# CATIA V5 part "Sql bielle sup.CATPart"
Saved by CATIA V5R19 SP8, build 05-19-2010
Part number: Sql bielle sup
Publications: "Droite.1", "Plan.1", "Droite.2", "Droite.3"
Bounding box of the stored display mesh (mm): x 100 to 400, y -20 to 20, z 0 to 0
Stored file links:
  C:\Users\ThinkMotion\Desktop\EU_thinkMotion\iao\IAO_MMS_Groupe3\rdalborgo\rdalborgo\Sql bielle sup.CATPart
  C:\Users\ThinkMotion\Desktop\EU_thinkMotion\iao\IAO_MMS_Groupe3\rdalborgo\rdalborgo\Sql train.CATProduct
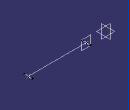
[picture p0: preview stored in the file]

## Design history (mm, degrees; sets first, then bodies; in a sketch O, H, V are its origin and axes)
Set1
  Point1 "A bielle": linked copy from another document
  Point2 "B bielle": linked copy from another document
  Plane1: linked copy from another document
Set2
  Line1: type PtPt, FirstPoint Point1, SecondPoint Point2
  Plane2: type OffsetPt, RefPlane Plane1, RefPoint Point1
  Line2: type Normal, RefPoint Point1, RefSkin Plane1, Start -20, End 20
  Line3: type Normal, RefPoint Point2, RefSkin Plane1, Start -20, End 20
Body1 (main body)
